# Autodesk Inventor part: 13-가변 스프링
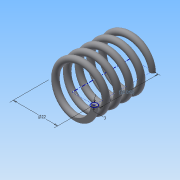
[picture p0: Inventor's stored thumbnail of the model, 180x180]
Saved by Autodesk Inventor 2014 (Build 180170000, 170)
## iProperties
Created: 2015-09
Part Number: 13-가변 스프링
Material: 강철, 탄소
Document SubType Name: Modeling
Designer: study
Density: 7.87 g/cm^3
Appearance: 반연마
Mass: 18.7976 g
Surface Area: 32.4648 cm^2
Volume: 2.38851 cm^3
Author: study
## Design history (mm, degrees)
sketch "스케치1"
  geometry: L1 (0, 0)-(11, 0); L2 (11, 0)-(11, 29.043); L3 (11, 29.043)-(0, 29.043); L4 (0, 29.043)-(0, 0); C1 r 1.5 at (11, 0)
  constraints: 8 end point, 2 parallel, 1 centre point, 1 coincident, 1 horizontal, 1 perpendicular
  dimensions: "d0" = 22 diameter of L2 L4; "d1" = 29.04259 distance of L1.end L2.end (derived); "d2" = 3 diameter of C1
feature "코일1" sketch "스케치1" pitch "d3" = 10; turns "d5" = 5; dims "d4" = 29.04259 (= d1), "d6" = 0, angle "d7" = 90 deg, angle "d8" = 90 deg, "d9" = 0, "d10" = 0
node "작업 평면1"
sketch "스케치2"
  geometry: L1 (-12.5, 0)-(-9.5, 0) reference; L2 (-12.5, 0)-(-9.5, 0) reference; 1 further point
  constraints: 2 horizontal alignment
extrude "돌출1" cut sketch "스케치2" stored distance "d12" = 10; taper "d13" = 0 deg
node "작업 평면2"
sketch "스케치3"
  geometry: L1 (-9.5, 0)-(-12.5, 0) reference; 1 further point
  constraints: 1 horizontal alignment
extrude "돌출2" cut sketch "스케치3" stored distance "d15" = 10; taper "d16" = 0 deg
node "솔리드1"
node "절단 모서리 투영1"
node "절단 모서리 투영2"
node "절단 모서리 투영3"
other parameters: "d11" = 0, "d14" = 29.04259 (= d1)
